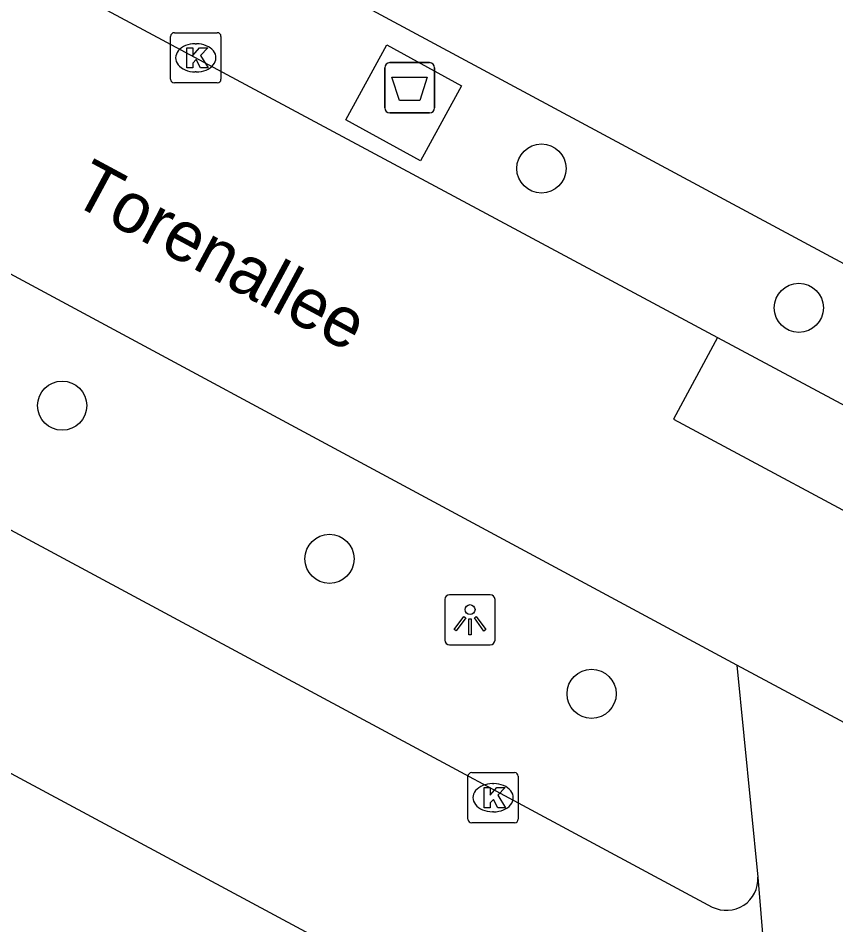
# Model space of a CAD drawing. Extents: x 159489 to 160304, y 383826 to 384530.
# Drawn here: x 159684.45 to 159700.71, y 384260.03 to 384278.07 of the extents above; entities that cross this region are included whole.
import ezdxf

# ---------------------------------------------------------------- set-up
doc = ezdxf.new("R2010")
doc.units = 0
for name, color, linetype in [('IMGEO_Afval_apart_plaats', 7, 'Continuous'), ('IMGEO_Boom', 7, 'Continuous'), ('IMGEO_Kolk', 7, 'Continuous'), ('IMGEO_Lichtpunt', 7, 'Continuous'), ('IMGEO_Openbare_ruimte_label', 7, 'Continuous'), ('IMGEO_Rijbaan_lokaal_gesloten', 7, 'Continuous'), ('IMGEO_Voetgangersgebied_gesloten', 7, 'Continuous'), ('IMGEO_Voetpad_gesloten', 7, 'Continuous'), ('IMGEO_Voetpad_open', 7, 'Continuous')]:
    doc.layers.add(name, color=color, linetype=linetype)

msp = doc.modelspace()

# ---------------------------------------------------------------- linework, layer by layer
at = {"layer": 'IMGEO_Afval_apart_plaats'}
for p, q in [((159691.741, 384276.284), (159691.741, 384277.084)), ((159691.741, 384277.084), (159691.741, 384276.284)), ((159691.841, 384277.184), (159692.631, 384277.184)), ((159692.631, 384277.184), (159691.841, 384277.184)), ((159692.731, 384277.084), (159692.731, 384276.284)), ((159692.731, 384276.284), (159692.731, 384277.084)), ((159692.631, 384276.184), (159691.841, 384276.184)), ((159691.841, 384276.184), (159692.631, 384276.184))]:
    msp.add_line(p, q, dxfattribs=at)
msp.add_lwpolyline([(159691.884, 384276.898), (159692.588, 384276.898), (159692.439, 384276.428), (159692.033, 384276.428), (159691.884, 384276.898)], dxfattribs=at)
for centre, start, end in [((159691.841, 384277.084), 90, 180), ((159691.841, 384277.084), 90, 180), ((159692.631, 384277.084), 0, 90), ((159692.631, 384277.084), 360, 90), ((159691.841, 384276.284), 180, 270), ((159691.841, 384276.284), 180, 270), ((159692.631, 384276.284), 270, 0), ((159692.631, 384276.284), 270, 0)]:
    msp.add_arc(centre, 0.1, start, end, dxfattribs=at)
at = {"layer": 'IMGEO_Boom'}
for centre in [(159694.857, 384275.079), (159699.975, 384272.308), (159685.325, 384270.361), (159690.641, 384267.314), (159695.855, 384264.63)]:
    msp.add_circle(centre, 0.489, dxfattribs=at)
at = {"layer": 'IMGEO_Kolk'}
for p, q in [((159687.558, 384277.78), (159688.41, 384277.78)), ((159687.483, 384276.854), (159687.483, 384277.706)), ((159687.971, 384277.56), (159687.996, 384277.56)), ((159688.484, 384277.706), (159688.484, 384276.854)), ((159687.994, 384277), (159687.969, 384277)), ((159688.41, 384276.78), (159687.558, 384276.78)), ((159693.396, 384262.136), (159693.396, 384262.988)), ((159693.471, 384263.062), (159694.323, 384263.062)), ((159694.397, 384262.988), (159694.397, 384262.136)), ((159693.884, 384262.842), (159693.909, 384262.842)), ((159693.907, 384262.282), (159693.882, 384262.282)), ((159694.323, 384262.062), (159693.471, 384262.062))]:
    msp.add_line(p, q, dxfattribs=at)
for points in [[(159687.558, 384277.78), (159688.41, 384277.78)], [(159687.483, 384276.854), (159687.483, 384277.706)], [(159688.484, 384277.706), (159688.484, 384276.854)], [(159687.804, 384277.48), (159687.927, 384277.48), (159687.927, 384277.329), (159688.057, 384277.48), (159688.221, 384277.48), (159688.075, 384277.329), (159688.228, 384277.08), (159688.076, 384277.08), (159687.991, 384277.244), (159687.927, 384277.177), (159687.927, 384277.08), (159687.804, 384277.08), (159687.804, 384277.48)], [(159688.41, 384276.78), (159687.558, 384276.78)], [(159693.396, 384262.136), (159693.396, 384262.988)], [(159693.471, 384263.062), (159694.323, 384263.062)], [(159694.397, 384262.988), (159694.397, 384262.136)], [(159693.717, 384262.762), (159693.84, 384262.762), (159693.84, 384262.611), (159693.97, 384262.762), (159694.134, 384262.762), (159693.988, 384262.611), (159694.141, 384262.362), (159693.989, 384262.362), (159693.904, 384262.526), (159693.84, 384262.459), (159693.84, 384262.362), (159693.717, 384262.362), (159693.717, 384262.762)], [(159694.323, 384262.062), (159693.471, 384262.062)]]:
    msp.add_lwpolyline(points, dxfattribs=at)
for centre, start, end in [((159687.56, 384277.704), 91.552, 178.448), ((159687.56, 384277.704), 91.552, 178.448), ((159688.408, 384277.704), 1.552, 88.448), ((159688.408, 384277.704), 1.552, 88.448), ((159687.56, 384276.856), 181.552, 268.448), ((159687.56, 384276.856), 181.552, 268.448), ((159688.408, 384276.856), 271.552, 358.448), ((159688.408, 384276.856), 271.552, 358.448), ((159693.473, 384262.986), 91.552, 178.448), ((159693.473, 384262.986), 91.552, 178.448), ((159694.321, 384262.986), 1.552, 88.448), ((159694.321, 384262.986), 1.552, 88.448), ((159693.473, 384262.138), 181.552, 268.448), ((159693.473, 384262.138), 181.552, 268.448), ((159694.321, 384262.138), 271.552, 358.448), ((159694.321, 384262.138), 271.552, 358.448)]:
    msp.add_arc(centre, 0.0765, start, end, dxfattribs=at)
for centre, major_axis, ratio, start_param, end_param in [((159687.97, 384277.28), (-0.387, 0.002), 0.722429, 4.712389, 7.853982), ((159687.995, 384277.28), (-0.39, 0.002), 0.717154, 1.570796, 4.712389), ((159693.883, 384262.562), (-0.387, 0.002), 0.722429, 4.712389, 7.853982), ((159693.908, 384262.562), (-0.39, 0.002), 0.717154, 1.570796, 4.712389)]:
    msp.add_ellipse(centre, major_axis=major_axis, ratio=ratio, start_param=start_param, end_param=end_param, dxfattribs=at)
at = {"layer": 'IMGEO_Lichtpunt'}
for p, q in [((159693.84, 384266.6), (159693.032, 384266.6)), ((159693.84, 384266.6), (159693.032, 384266.6)), ((159692.938, 384266.505), (159692.938, 384265.698)), ((159692.938, 384266.505), (159692.938, 384265.698)), ((159693.934, 384265.698), (159693.934, 384266.505)), ((159693.934, 384265.698), (159693.934, 384266.505)), ((159693.032, 384265.604), (159693.84, 384265.604)), ((159693.032, 384265.604), (159693.84, 384265.604))]:
    msp.add_line(p, q, dxfattribs=at)
for points in [[(159693.312, 384266.169), (159693.351, 384266.141), (159693.163, 384265.879), (159693.125, 384265.906), (159693.312, 384266.169)], [(159693.414, 384266.121), (159693.461, 384266.121), (159693.461, 384265.799), (159693.414, 384265.799), (159693.414, 384266.121)], [(159693.524, 384266.141), (159693.562, 384266.168), (159693.749, 384265.906), (159693.71, 384265.878), (159693.524, 384266.141)]]:
    msp.add_lwpolyline(points, dxfattribs=at)
msp.add_circle((159693.437, 384266.303), 0.0994, dxfattribs=at)
for centre, start, end in [((159693.032, 384266.505), 90, 180), ((159693.032, 384266.505), 90, 180), ((159693.84, 384266.505), 0, 90), ((159693.84, 384266.505), 0, 90), ((159693.032, 384265.698), 180, 270), ((159693.032, 384265.698), 180, 270), ((159693.84, 384265.698), 270, 0), ((159693.84, 384265.698), 270, 360)]:
    msp.add_arc(centre, 0.0946, start, end, dxfattribs=at)
at = {"layer": 'IMGEO_Rijbaan_lokaal_gesloten'}
for points in [[(159698.746, 384265.2), (159658.313, 384286.981)], [(159675.705, 384283.863), (159698.359, 384271.717)], [(159698.359, 384271.717), (159697.486, 384270.09), (159702.303, 384267.507), (159703.175, 384269.135)], [(159711.716, 384258.252), (159698.746, 384265.2)]]:
    msp.add_lwpolyline(points, dxfattribs=at)
at = {"layer": 'IMGEO_Voetgangersgebied_gesloten'}
msp.add_lwpolyline([(159698.746, 384265.2), (159699.162, 384260.982)], dxfattribs=at)
at = {"layer": 'IMGEO_Voetpad_gesloten'}
for points in [[(159657.072, 384282.538), (159698.254, 384260.388)], [(159699.221, 384255.028), (159655.026, 384278.787)], [(159693.267, 384276.721), (159692.562, 384275.436), (159692.45, 384275.232), (159690.964, 384276.048), (159691.781, 384277.537), (159693.267, 384276.721)], [(159699.162, 384260.982), (159699.72, 384254.238)]]:
    msp.add_lwpolyline(points, dxfattribs=at)
msp.add_arc((159698.536, 384260.948), 0.627, 243.2486, 3.1356, dxfattribs=at)
at = {"layer": 'IMGEO_Voetpad_open'}
for points in [[(159778.522, 384238.137), (159775.75, 384232.935), (159674.737, 384287.233), (159677.536, 384292.428), (159778.522, 384238.137)], [(159698.359, 384271.717), (159703.175, 384269.135)]]:
    msp.add_lwpolyline(points, dxfattribs=at)

# ---------------------------------------------------------------- texts
at = {"layer": 'IMGEO_Openbare_ruimte_label'}
msp.add_text('Torenallee', height=1, rotation=331.6915, dxfattribs=at).set_placement((159685.464, 384274.414))

doc.saveas('drawing.dxf')
